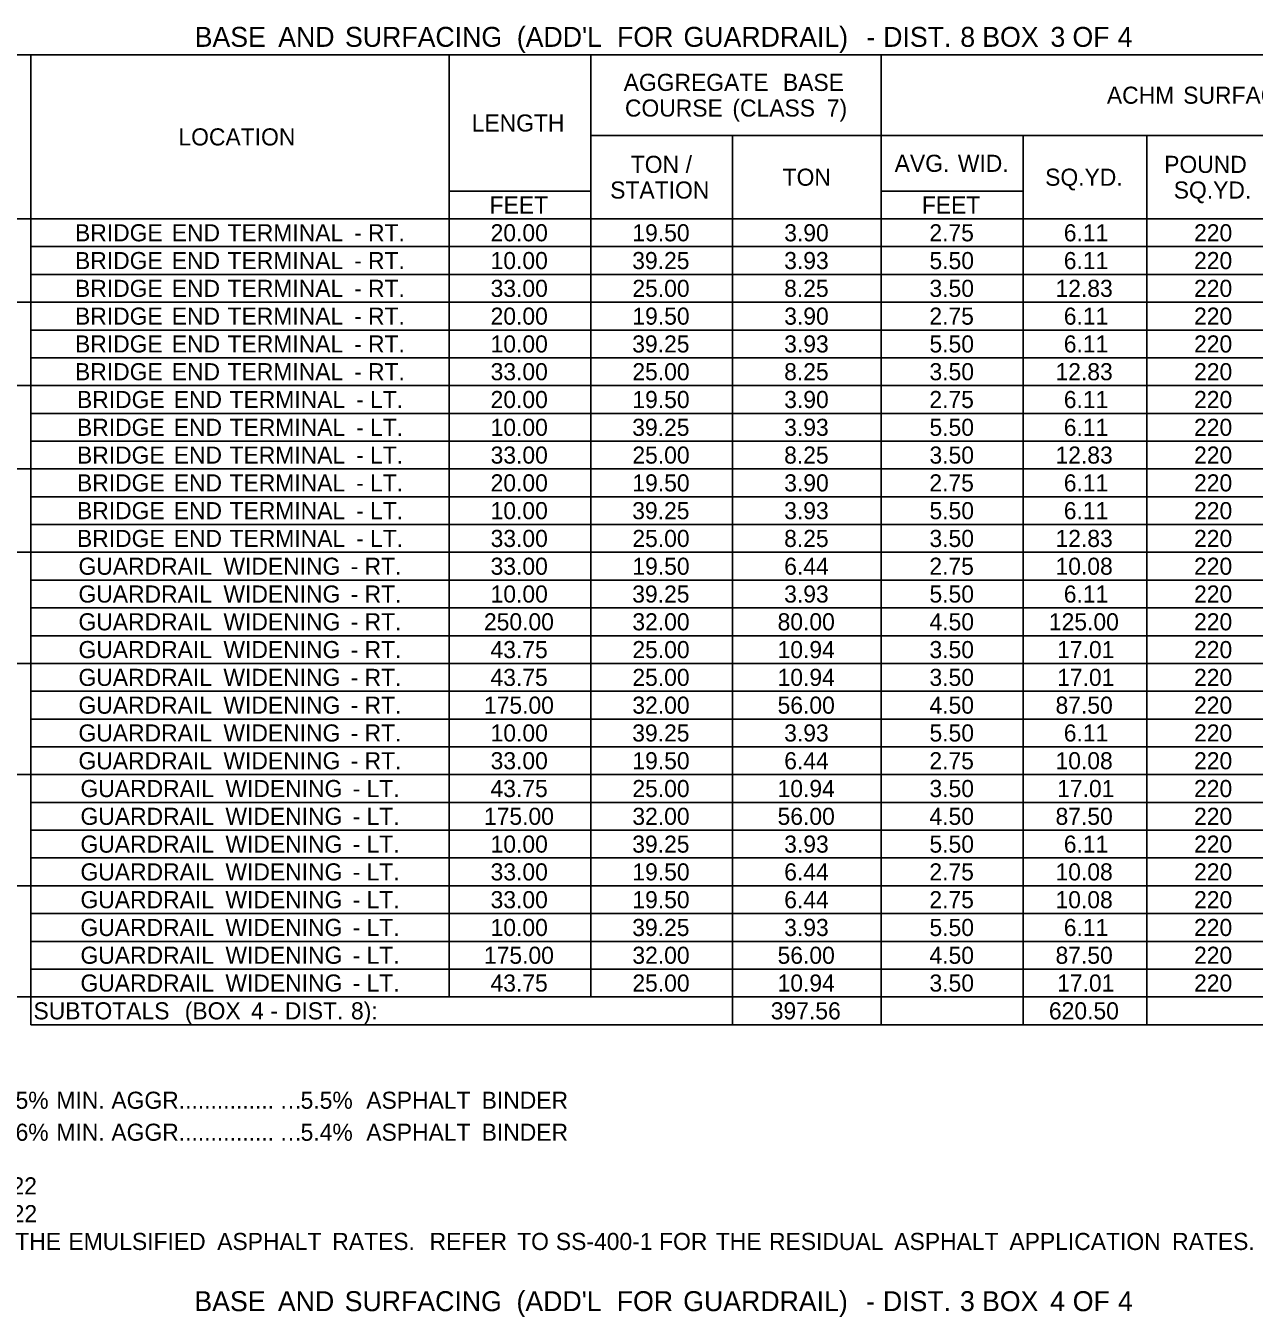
# Model space of a CAD drawing. Extents: x 540541 to 1930787, y -1948574 to 596640.
# Drawn here: x 559893 to 560323.8, y -1946465.6 to -1946012.5 of the extents above; entities that cross this region are included whole.
import ezdxf

# ---------------------------------------------------------------- set-up
doc = ezdxf.new("R2010")
doc.units = 0
doc.layers.add('Default', color=7, linetype='Continuous')

msp = doc.modelspace()

# ---------------------------------------------------------------- linework, layer by layer
at = {"layer": 'Default'}
for p, q in [((559673.34, -1946022.69), (560560.1, -1946022.69)), ((559894.67, -1946362.96), (559894.67, -1946022.69)), ((560041.4, -1946353.21), (560041.4, -1946022.69)), ((560091.13, -1946353.21), (560091.13, -1946022.69)), ((560193.02, -1946362.96), (560193.02, -1946022.69)), ((560091.13, -1946050.96), (560560.1, -1946050.96)), ((560140.85, -1946362.96), (560140.85, -1946050.96)), ((560242.74, -1946050.96), (560286.13, -1946050.96)), ((560242.74, -1946362.96), (560242.74, -1946050.96)), ((560286.13, -1946362.96), (560286.13, -1946050.96)), ((560041.4, -1946070.46), (560091.13, -1946070.46)), ((560091.13, -1946353.21), (560091.13, -1946070.46)), ((560193.02, -1946070.46), (560242.74, -1946070.46)), ((560193.02, -1946080.21), (560193.02, -1946070.46)), ((560242.74, -1946362.96), (560242.74, -1946070.46)), ((559673.34, -1946080.21), (560091.13, -1946080.21)), ((559844.94, -1946080.21), (559894.67, -1946080.21)), ((560091.13, -1946080.21), (560242.74, -1946080.21)), ((560140.85, -1946362.96), (560140.85, -1946080.21)), ((560242.74, -1946080.21), (560560.1, -1946080.21)), ((560286.13, -1946362.96), (560286.13, -1946080.21)), ((559894.67, -1946089.96), (560560.1, -1946089.96)), ((560041.4, -1946109.46), (560041.4, -1946089.96)), ((559894.67, -1946099.71), (560560.1, -1946099.71)), ((559844.94, -1946109.46), (560560.1, -1946109.46)), ((559894.67, -1946119.21), (560560.1, -1946119.21)), ((560041.4, -1946138.71), (560041.4, -1946119.21)), ((559894.67, -1946128.96), (560560.1, -1946128.96)), ((559844.94, -1946138.71), (560560.1, -1946138.71)), ((559894.67, -1946148.46), (560560.1, -1946148.46)), ((559894.67, -1946158.21), (560560.1, -1946158.21)), ((559844.94, -1946167.96), (560560.1, -1946167.96)), ((559894.67, -1946177.71), (560560.1, -1946177.71)), ((559894.67, -1946187.46), (560560.1, -1946187.46)), ((559673.34, -1946197.21), (560479.18, -1946197.21)), ((559844.94, -1946197.21), (559894.67, -1946197.21)), ((559894.67, -1946197.21), (560332.93, -1946197.21)), ((560041.4, -1946353.21), (560041.4, -1946197.21)), ((559894.67, -1946206.96), (560560.1, -1946206.96)), ((559894.67, -1946216.71), (560560.1, -1946216.71)), ((559894.67, -1946226.46), (560560.1, -1946226.46)), ((559844.94, -1946236.21), (560560.1, -1946236.21)), ((559894.67, -1946245.96), (560560.1, -1946245.96)), ((559894.67, -1946255.71), (560560.1, -1946255.71)), ((559894.67, -1946265.46), (560560.1, -1946265.46)), ((559844.94, -1946275.21), (560560.1, -1946275.21)), ((559894.67, -1946284.96), (560560.1, -1946284.96)), ((559894.67, -1946294.71), (560560.1, -1946294.71)), ((559894.67, -1946304.46), (560560.1, -1946304.46)), ((559844.94, -1946314.21), (560193.02, -1946314.21)), ((560140.85, -1946314.21), (560193.02, -1946314.21)), ((560193.02, -1946314.21), (560560.1, -1946314.21)), ((559894.67, -1946323.96), (560560.1, -1946323.96)), ((559894.67, -1946333.71), (560193.02, -1946333.71)), ((560140.85, -1946333.71), (560193.02, -1946333.71)), ((560193.02, -1946333.71), (560560.1, -1946333.71)), ((559894.67, -1946343.46), (560193.02, -1946343.46)), ((560140.85, -1946343.46), (560193.02, -1946343.46)), ((560193.02, -1946343.46), (560560.1, -1946343.46)), ((559673.34, -1946353.21), (560560.1, -1946353.21)), ((559894.67, -1946362.96), (559894.67, -1946353.21)), ((560193.02, -1946362.96), (560193.02, -1946353.21)), ((559894.67, -1946362.96), (560560.1, -1946362.96))]:
    msp.add_line(p, q, dxfattribs=at)

# ---------------------------------------------------------------- texts
for s, height, p in [('BASE', 7, (559952.18, -1946019.85)), (' AND', 7, (559978.88, -1946019.85)), (' SURFACING', 7, (560002.3, -1946019.85)), (" (ADD'L", 7, (560062.57, -1946019.85)), (' FOR', 7, (560097.74, -1946019.85)), (' GUARDRAIL)', 7, (560121.05, -1946019.85)), (' DIST.', 7, (560191.1, -1946019.85)), (' 8', 7, (560218.14, -1946019.85)), (' BOX', 7, (560225.85, -1946019.85)), (' 3', 7, (560249.76, -1946019.85)), (' OF', 7, (560257.49, -1946019.85)), (' 4', 7, (560273.33, -1946019.85)), (' -', 7, (560185.2, -1946019.85)), ('AGGREGATE', 6, (560102.66, -1946035.32)), (' BASE', 6, (560156.28, -1946035.32)), ('ACHM', 6, (560272.16, -1946039.82)), (' SURFACE', 6, (560296.71, -1946039.82)), ('COURSE', 6, (560103.11, -1946044.32)), (' (CLASS', 6, (560138.57, -1946044.32)), (' 7)', 6, (560171.69, -1946044.32)), ('LENGTH', 6, (560049.35, -1946049.57)), ('LOCATION', 6, (559946.48, -1946054.45)), ('TON', 6, (560105.15, -1946064.09)), (' /', 6, (560122.17, -1946064.09)), ('AVG.', 6, (560197.73, -1946063.71)), (' WID.', 6, (560217.65, -1946063.71)), ('POUND', 6, (560292.26, -1946064.09)), ('TON', 6, (560158.42, -1946068.59)), ('SQ.YD.', 6, (560250.51, -1946068.59)), ('STATION', 6, (560097.93, -1946073.09)), ('SQ.YD.', 6, (560295.61, -1946073.09)), ('FEET', 6, (560055.64, -1946078.34)), ('FEET', 6, (560207.25, -1946078.34)), ('BRIDGE', 6, (559910.21, -1946088.09)), (' END', 6, (559941.9, -1946088.09)), (' TERMINAL', 6, (559961.49, -1946088.09)), (' -', 6, (560005.91, -1946088.09)), (' RT.', 6, (560010.76, -1946088.09)), ('20.00', 6, (560055.98, -1946088.09)), ('19.50', 6, (560105.71, -1946088.09)), ('3.90', 6, (560158.98, -1946088.09)), ('2.75', 6, (560209.89, -1946088.09)), ('6.11', 6, (560257.05, -1946088.09)), ('220', 6, (560302.74, -1946088.09)), ('BRIDGE', 6, (559910.21, -1946097.84)), (' END', 6, (559941.9, -1946097.84)), (' TERMINAL', 6, (559961.49, -1946097.84)), (' -', 6, (560005.91, -1946097.84)), (' RT.', 6, (560010.76, -1946097.84)), ('10.00', 6, (560055.98, -1946097.84)), ('39.25', 6, (560105.67, -1946097.84)), ('3.93', 6, (560158.97, -1946097.84)), ('5.50', 6, (560209.93, -1946097.84)), ('6.11', 6, (560257.05, -1946097.84)), ('220', 6, (560302.74, -1946097.84)), ('BRIDGE', 6, (559910.21, -1946107.59)), (' END', 6, (559941.9, -1946107.59)), (' TERMINAL', 6, (559961.49, -1946107.59)), (' RT.', 6, (560010.76, -1946107.59)), ('33.00', 6, (560055.98, -1946107.59)), ('25.00', 6, (560105.71, -1946107.59)), ('8.25', 6, (560158.95, -1946107.59)), ('3.50', 6, (560209.93, -1946107.59)), ('12.83', 6, (560254.14, -1946107.59)), ('220', 6, (560302.74, -1946107.59)), (' -', 6, (560005.91, -1946107.59)), ('BRIDGE', 6, (559910.21, -1946117.34)), (' END', 6, (559941.9, -1946117.34)), (' TERMINAL', 6, (559961.49, -1946117.34)), (' RT.', 6, (560010.76, -1946117.34)), ('20.00', 6, (560055.98, -1946117.34)), ('19.50', 6, (560105.71, -1946117.34)), ('3.90', 6, (560158.98, -1946117.34)), ('2.75', 6, (560209.89, -1946117.34)), ('6.11', 6, (560257.05, -1946117.34)), ('220', 6, (560302.74, -1946117.34)), (' -', 6, (560005.91, -1946117.34)), ('BRIDGE', 6, (559910.21, -1946127.09)), (' END', 6, (559941.9, -1946127.09)), (' TERMINAL', 6, (559961.49, -1946127.09)), (' RT.', 6, (560010.76, -1946127.09)), ('10.00', 6, (560055.98, -1946127.09)), ('39.25', 6, (560105.67, -1946127.09)), ('3.93', 6, (560158.97, -1946127.09)), ('5.50', 6, (560209.93, -1946127.09)), ('6.11', 6, (560257.05, -1946127.09)), ('220', 6, (560302.74, -1946127.09)), (' -', 6, (560005.91, -1946127.09)), ('BRIDGE', 6, (559910.21, -1946136.84)), (' END', 6, (559941.9, -1946136.84)), (' TERMINAL', 6, (559961.49, -1946136.84)), (' RT.', 6, (560010.76, -1946136.84)), ('33.00', 6, (560055.98, -1946136.84)), ('25.00', 6, (560105.71, -1946136.84)), ('8.25', 6, (560158.95, -1946136.84)), ('3.50', 6, (560209.93, -1946136.84)), ('12.83', 6, (560254.14, -1946136.84)), ('220', 6, (560302.74, -1946136.84)), (' -', 6, (560005.91, -1946136.84)), ('BRIDGE', 6, (559910.9, -1946146.59)), (' END', 6, (559942.6, -1946146.59)), (' TERMINAL', 6, (559962.18, -1946146.59)), (' LT.', 6, (560011.46, -1946146.59)), ('20.00', 6, (560055.98, -1946146.59)), ('19.50', 6, (560105.71, -1946146.59)), ('3.90', 6, (560158.98, -1946146.59)), ('2.75', 6, (560209.89, -1946146.59)), ('6.11', 6, (560257.05, -1946146.59)), ('220', 6, (560302.74, -1946146.59)), (' -', 6, (560006.6, -1946146.59)), ('BRIDGE', 6, (559910.9, -1946156.34)), (' END', 6, (559942.6, -1946156.34)), (' TERMINAL', 6, (559962.18, -1946156.34)), (' -', 6, (560006.6, -1946156.34)), (' LT.', 6, (560011.46, -1946156.34)), ('10.00', 6, (560055.98, -1946156.34)), ('39.25', 6, (560105.67, -1946156.34)), ('3.93', 6, (560158.97, -1946156.34)), ('5.50', 6, (560209.93, -1946156.34)), ('6.11', 6, (560257.05, -1946156.34)), ('220', 6, (560302.74, -1946156.34)), ('BRIDGE', 6, (559910.9, -1946166.09)), (' END', 6, (559942.6, -1946166.09)), (' TERMINAL', 6, (559962.18, -1946166.09)), (' -', 6, (560006.6, -1946166.09)), (' LT.', 6, (560011.46, -1946166.09)), ('33.00', 6, (560055.98, -1946166.09)), ('25.00', 6, (560105.71, -1946166.09)), ('8.25', 6, (560158.95, -1946166.09)), ('3.50', 6, (560209.93, -1946166.09)), ('12.83', 6, (560254.14, -1946166.09)), ('220', 6, (560302.74, -1946166.09)), ('BRIDGE', 6, (559910.9, -1946175.84)), (' END', 6, (559942.6, -1946175.84)), (' TERMINAL', 6, (559962.18, -1946175.84)), (' LT.', 6, (560011.46, -1946175.84)), ('20.00', 6, (560055.98, -1946175.84)), ('19.50', 6, (560105.71, -1946175.84)), ('3.90', 6, (560158.98, -1946175.84)), ('2.75', 6, (560209.89, -1946175.84)), ('6.11', 6, (560257.05, -1946175.84)), ('220', 6, (560302.74, -1946175.84)), (' -', 6, (560006.6, -1946175.84)), ('BRIDGE', 6, (559910.9, -1946185.59)), (' END', 6, (559942.6, -1946185.59)), (' TERMINAL', 6, (559962.18, -1946185.59)), (' LT.', 6, (560011.46, -1946185.59)), ('10.00', 6, (560055.98, -1946185.59)), ('39.25', 6, (560105.67, -1946185.59)), ('3.93', 6, (560158.97, -1946185.59)), ('5.50', 6, (560209.93, -1946185.59)), ('6.11', 6, (560257.05, -1946185.59)), ('220', 6, (560302.74, -1946185.59)), (' -', 6, (560006.6, -1946185.59)), ('BRIDGE', 6, (559910.9, -1946195.34)), (' END', 6, (559942.6, -1946195.34)), (' TERMINAL', 6, (559962.18, -1946195.34)), (' LT.', 6, (560011.46, -1946195.34)), ('33.00', 6, (560055.98, -1946195.34)), ('25.00', 6, (560105.71, -1946195.34)), ('8.25', 6, (560158.95, -1946195.34)), ('3.50', 6, (560209.93, -1946195.34)), ('12.83', 6, (560254.14, -1946195.34)), ('220', 6, (560302.74, -1946195.34)), (' -', 6, (560006.6, -1946195.34)), ('GUARDRAIL', 6, (559911.42, -1946205.09)), (' WIDENING', 6, (559960.04, -1946205.09)), (' RT.', 6, (560009.55, -1946205.09)), ('33.00', 6, (560055.98, -1946205.09)), ('19.50', 6, (560105.71, -1946205.09)), ('6.44', 6, (560158.98, -1946205.09)), ('2.75', 6, (560209.89, -1946205.09)), ('10.08', 6, (560254.14, -1946205.09)), ('220', 6, (560302.74, -1946205.09)), (' -', 6, (560004.69, -1946205.09)), ('GUARDRAIL', 6, (559911.42, -1946214.84)), (' WIDENING', 6, (559960.04, -1946214.84)), ('10.00', 6, (560055.98, -1946214.84)), ('39.25', 6, (560105.67, -1946214.84)), ('3.93', 6, (560158.97, -1946214.84)), ('5.50', 6, (560209.93, -1946214.84)), ('6.11', 6, (560257.05, -1946214.84)), ('220', 6, (560302.74, -1946214.84)), (' -', 6, (560004.69, -1946214.84)), (' RT.', 6, (560009.55, -1946214.84)), ('GUARDRAIL', 6, (559911.42, -1946224.59)), (' WIDENING', 6, (559960.04, -1946224.59)), (' -', 6, (560004.69, -1946224.59)), (' RT.', 6, (560009.55, -1946224.59)), ('250.00', 6, (560053.65, -1946224.59)), ('32.00', 6, (560105.71, -1946224.59)), ('80.00', 6, (560156.65, -1946224.59)), ('4.50', 6, (560209.93, -1946224.59)), ('125.00', 6, (560251.82, -1946224.59)), ('220', 6, (560302.74, -1946224.59)), ('GUARDRAIL', 6, (559911.42, -1946234.34)), (' WIDENING', 6, (559960.04, -1946234.34)), (' RT.', 6, (560009.55, -1946234.34)), ('43.75', 6, (560055.95, -1946234.34)), ('25.00', 6, (560105.71, -1946234.34)), ('10.94', 6, (560156.65, -1946234.34)), ('3.50', 6, (560209.93, -1946234.34)), ('17.01', 6, (560254.72, -1946234.34)), ('220', 6, (560302.74, -1946234.34)), (' -', 6, (560004.69, -1946234.34)), ('GUARDRAIL', 6, (559911.42, -1946244.09)), (' WIDENING', 6, (559960.04, -1946244.09)), (' RT.', 6, (560009.55, -1946244.09)), ('43.75', 6, (560055.95, -1946244.09)), ('25.00', 6, (560105.71, -1946244.09)), ('10.94', 6, (560156.65, -1946244.09)), ('3.50', 6, (560209.93, -1946244.09)), ('17.01', 6, (560254.72, -1946244.09)), ('220', 6, (560302.74, -1946244.09)), (' -', 6, (560004.69, -1946244.09)), ('GUARDRAIL', 6, (559911.42, -1946253.84)), (' WIDENING', 6, (559960.04, -1946253.84)), (' RT.', 6, (560009.55, -1946253.84)), ('175.00', 6, (560053.65, -1946253.84)), ('32.00', 6, (560105.71, -1946253.84)), ('56.00', 6, (560156.65, -1946253.84)), ('4.50', 6, (560209.93, -1946253.84)), ('87.50', 6, (560254.15, -1946253.84)), ('220', 6, (560302.74, -1946253.84)), (' -', 6, (560004.69, -1946253.84)), ('GUARDRAIL', 6, (559911.42, -1946263.59)), (' WIDENING', 6, (559960.04, -1946263.59)), (' RT.', 6, (560009.55, -1946263.59)), ('10.00', 6, (560055.98, -1946263.59)), ('39.25', 6, (560105.67, -1946263.59)), ('3.93', 6, (560158.97, -1946263.59)), ('5.50', 6, (560209.93, -1946263.59)), ('6.11', 6, (560257.05, -1946263.59)), ('220', 6, (560302.74, -1946263.59)), (' -', 6, (560004.69, -1946263.59)), ('GUARDRAIL', 6, (559911.42, -1946273.34)), (' WIDENING', 6, (559960.04, -1946273.34)), (' RT.', 6, (560009.55, -1946273.34)), ('33.00', 6, (560055.98, -1946273.34)), ('19.50', 6, (560105.71, -1946273.34)), ('6.44', 6, (560158.98, -1946273.34)), ('2.75', 6, (560209.89, -1946273.34)), ('10.08', 6, (560254.14, -1946273.34)), ('220', 6, (560302.74, -1946273.34)), (' -', 6, (560004.69, -1946273.34)), ('GUARDRAIL', 6, (559912.12, -1946283.09)), (' WIDENING', 6, (559960.74, -1946283.09)), (' -', 6, (560005.39, -1946283.09)), (' LT.', 6, (560010.24, -1946283.09)), ('43.75', 6, (560055.95, -1946283.09)), ('25.00', 6, (560105.71, -1946283.09)), ('10.94', 6, (560156.65, -1946283.09)), ('3.50', 6, (560209.93, -1946283.09)), ('17.01', 6, (560254.72, -1946283.09)), ('220', 6, (560302.74, -1946283.09)), ('GUARDRAIL', 6, (559912.12, -1946292.84)), (' WIDENING', 6, (559960.74, -1946292.84)), (' -', 6, (560005.39, -1946292.84)), (' LT.', 6, (560010.24, -1946292.84)), ('175.00', 6, (560053.65, -1946292.84)), ('32.00', 6, (560105.71, -1946292.84)), ('56.00', 6, (560156.65, -1946292.84)), ('4.50', 6, (560209.93, -1946292.84)), ('87.50', 6, (560254.15, -1946292.84)), ('220', 6, (560302.74, -1946292.84)), ('GUARDRAIL', 6, (559912.12, -1946302.59)), (' WIDENING', 6, (559960.74, -1946302.59)), (' LT.', 6, (560010.24, -1946302.59)), ('10.00', 6, (560055.98, -1946302.59)), ('39.25', 6, (560105.67, -1946302.59)), ('3.93', 6, (560158.97, -1946302.59)), ('5.50', 6, (560209.93, -1946302.59)), ('6.11', 6, (560257.05, -1946302.59)), ('220', 6, (560302.74, -1946302.59)), (' -', 6, (560005.39, -1946302.59)), ('GUARDRAIL', 6, (559912.12, -1946312.34)), (' WIDENING', 6, (559960.74, -1946312.34)), (' LT.', 6, (560010.24, -1946312.34)), ('33.00', 6, (560055.98, -1946312.34)), ('19.50', 6, (560105.71, -1946312.34)), ('6.44', 6, (560158.98, -1946312.34)), ('2.75', 6, (560209.89, -1946312.34)), ('10.08', 6, (560254.14, -1946312.34)), ('220', 6, (560302.74, -1946312.34)), (' -', 6, (560005.39, -1946312.34)), ('GUARDRAIL', 6, (559912.12, -1946322.09)), (' WIDENING', 6, (559960.74, -1946322.09)), (' LT.', 6, (560010.24, -1946322.09)), ('33.00', 6, (560055.98, -1946322.09)), ('19.50', 6, (560105.71, -1946322.09)), ('6.44', 6, (560158.98, -1946322.09)), ('2.75', 6, (560209.89, -1946322.09)), ('10.08', 6, (560254.14, -1946322.09)), ('220', 6, (560302.74, -1946322.09)), (' -', 6, (560005.39, -1946322.09)), ('GUARDRAIL', 6, (559912.12, -1946331.84)), (' WIDENING', 6, (559960.74, -1946331.84)), (' LT.', 6, (560010.24, -1946331.84)), ('10.00', 6, (560055.98, -1946331.84)), ('39.25', 6, (560105.67, -1946331.84)), ('3.93', 6, (560158.97, -1946331.84)), ('5.50', 6, (560209.93, -1946331.84)), ('6.11', 6, (560257.05, -1946331.84)), ('220', 6, (560302.74, -1946331.84)), (' -', 6, (560005.39, -1946331.84)), ('GUARDRAIL', 6, (559912.12, -1946341.59)), (' WIDENING', 6, (559960.74, -1946341.59)), (' LT.', 6, (560010.24, -1946341.59)), ('175.00', 6, (560053.65, -1946341.59)), ('32.00', 6, (560105.71, -1946341.59)), ('56.00', 6, (560156.65, -1946341.59)), ('4.50', 6, (560209.93, -1946341.59)), ('87.50', 6, (560254.15, -1946341.59)), ('220', 6, (560302.74, -1946341.59)), (' -', 6, (560005.39, -1946341.59)), ('GUARDRAIL', 6, (559912.12, -1946351.34)), (' WIDENING', 6, (559960.74, -1946351.34)), (' -', 6, (560005.39, -1946351.34)), (' LT.', 6, (560010.24, -1946351.34)), ('43.75', 6, (560055.95, -1946351.34)), ('25.00', 6, (560105.71, -1946351.34)), ('10.94', 6, (560156.65, -1946351.34)), ('3.50', 6, (560209.93, -1946351.34)), ('17.01', 6, (560254.72, -1946351.34)), ('220', 6, (560302.74, -1946351.34)), ('SUBTOTALS', 6, (559895.64, -1946361.09)), (' (BOX', 6, (559946.47, -1946361.09)), (' 4', 6, (559969.74, -1946361.09)), (' DIST.', 6, (559981.6, -1946361.09)), (' 8):', 6, (560004.78, -1946361.09)), ('397.56', 6, (560154.27, -1946361.09)), ('620.50', 6, (560251.83, -1946361.09)), (' -', 6, (559976.54, -1946361.09)), ('94.5%', 6, (559878.2, -1946392.47)), (' MIN.', 6, (559901.44, -1946392.47)), (' AGGR...............', 6, (559920.73, -1946392.47)), ('5.5%', 6, (559989.33, -1946392.47)), ('  ASPHALT', 6, (560007.92, -1946392.47)), (' BINDER', 6, (560050.61, -1946392.47)), ('…', 6, (559981.94, -1946392.47)), ('94.6%', 6, (559878.2, -1946403.69)), (' MIN.', 6, (559901.44, -1946403.69)), (' AGGR...............', 6, (559920.73, -1946403.69)), ('5.4%', 6, (559989.33, -1946403.69)), ('  ASPHALT', 6, (560007.92, -1946403.69)), (' BINDER', 6, (560050.61, -1946403.69)), ('…', 6, (559981.94, -1946403.69)), (' 70-22', 6, (559874.1, -1946422.51)), (' 76-22', 6, (559874.16, -1946432.26)), (' THE', 6, (559887.01, -1946442.01)), (' EMULSIFIED', 6, (559905.66, -1946442.01)), (' ASPHALT', 6, (559957.85, -1946442.01)), (' RATES.', 6, (559998.22, -1946442.01)), ('  REFER', 6, (560030.1, -1946442.01)), (' TO', 6, (560063.06, -1946442.01)), (' SS-400-1', 6, (560076.65, -1946442.01)), (' FOR', 6, (560112.85, -1946442.01)), (' THE', 6, (560132.76, -1946442.01)), (' RESIDUAL', 6, (560151.41, -1946442.01)), (' ASPHALT', 6, (560195.37, -1946442.01)), (' APPLICATION', 6, (560235.74, -1946442.01)), (' RATES.', 6, (560292.82, -1946442.01)), ('BASE', 7, (559952.08, -1946463.47)), (' AND', 7, (559978.77, -1946463.47)), (' SURFACING', 7, (560002.19, -1946463.47)), (" (ADD'L", 7, (560062.46, -1946463.47)), (' FOR', 7, (560097.63, -1946463.47)), (' GUARDRAIL)', 7, (560120.95, -1946463.47)), (' DIST.', 7, (560190.99, -1946463.47)), (' 3', 7, (560218.03, -1946463.47)), (' BOX', 7, (560225.76, -1946463.47)), (' 4', 7, (560249.67, -1946463.47)), (' OF', 7, (560257.59, -1946463.47)), (' 4', 7, (560273.44, -1946463.47)), (' -', 7, (560185.09, -1946463.47))]:
    msp.add_text(s, height=height, dxfattribs=at).set_placement(p)

doc.saveas('drawing.dxf')
